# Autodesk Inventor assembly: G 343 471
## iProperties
Company: Mayer & Müller AG
Created: 2006-06
Part Number: G 343 471
Document SubType Name: Assembly
Designer: I.Baliuc
Description: Seitenteil, kompl. (rechts)
Mass: 2064.37 g
Surface Area: 1799.36 cm^2
Volume: 263.177 cm^3
Density: 7.84404 g/cm^3
Zweck: Vorkontakt HSLT
Author: T.Messerschmitt
Revision Number: 343471
